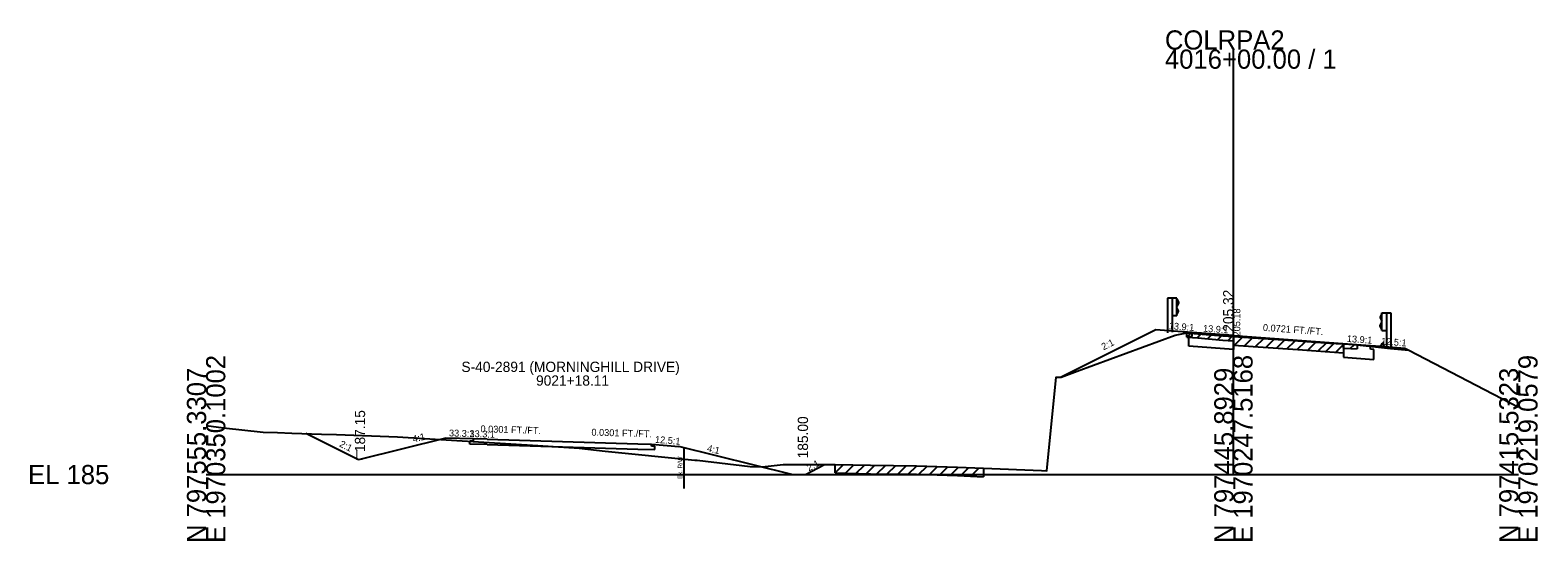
# Model space of a CAD drawing. Extents: x -26 to 1971083, y -10 to 798159.
# Drawn here: x -25.7 to 194.5, y 490.3 to 564.9 of the extents above; entities that cross this region are included whole.
import ezdxf

# ---------------------------------------------------------------- set-up
doc = ezdxf.new("R2010")
doc.units = 0
for name, color, linetype in [('RD_GPK_XS_Cell', 7, 'Continuous'), ('RD_XS_Base', 7, 'Continuous'), ('RD_XS_CurbTop', 7, 'Continuous'), ('RD_XS_EarthShd', 7, 'Continuous'), ('RD_XS_ExGround', 7, 'Continuous'), ('RD_XS_ExPaveRet', 7, 'Continuous'), ('RD_XS_ExRW', 7, 'Continuous'), ('RD_XS_GR', 7, 'Continuous'), ('RD_XS_Misc_Line', 7, 'Continuous'), ('RD_XS_Pave', 7, 'Continuous'), ('RD_XS_PaveOvlay', 7, 'Continuous'), ('RD_XS_PaveShd', 7, 'Continuous'), ('RD_XS_TieSlope', 7, 'Continuous'), ('RD_XS_TX_Elev_EX', 7, 'Continuous'), ('RD_XS_TX_Elev_PR', 7, 'Continuous'), ('RD_XS_TX_Misc', 7, 'Continuous'), ('RD_XS_TX_MkPT', 7, 'Continuous'), ('RD_XS_TX_Profile', 7, 'Continuous'), ('RD_XS_TX_ShdSlope', 7, 'Continuous'), ('RD_XS_TX_Slope', 7, 'Continuous'), ('RD_XS_TX_Station', 7, 'Continuous')]:
    doc.layers.add(name, color=color, linetype=linetype)

msp = doc.modelspace()

# ---------------------------------------------------------------- linework, layer by layer
at = {"layer": 'RD_GPK_XS_Cell'}
for p, q in [((150, 500), (150, 562.11)), ((0, 500), (150, 500)), ((150, 500), (191.61, 500))]:
    msp.add_line(p, q, dxfattribs=at)
at = {"layer": 'RD_XS_Base'}
for p, q in [((143.5, 520.22), (144, 520.19)), ((143.5, 518.74), (143.5, 520.22)), ((144, 520.19), (144, 520.75)), ((150, 518.28), (143.5, 518.74)), ((170, 518.32), (170, 518.88)), ((170.5, 518.29), (170, 518.32)), ((170.5, 516.81), (170.5, 518.29)), ((166.09, 517.13), (170.5, 516.81)), ((38.52, 504.94), (39.02, 504.92)), ((38.52, 504.46), (38.52, 504.94)), ((41.02, 504.38), (38.52, 504.46)), ((39.02, 504.92), (39.02, 505.22)), ((41.02, 504.38), (52.02, 504.05)), ((65.02, 504.14), (65.02, 504.44)), ((65.52, 504.13), (65.02, 504.14)), ((52.02, 504.05), (63.02, 503.72)), ((63.02, 503.72), (65.52, 503.65)), ((65.52, 503.65), (65.52, 504.13))]:
    msp.add_line(p, q, dxfattribs=at)
at = {"layer": 'RD_XS_CurbTop'}
for p, q in [((171.53, 518.76), (171.78, 519.22)), ((171.53, 518.76), (172, 518.72)), ((172, 518.72), (171.94, 519.16))]:
    msp.add_line(p, q, dxfattribs=at)
msp.add_ellipse((171.85, 519.14), major_axis=(0, -0.131), ratio=0.686, start_param=1.762783, end_param=4.036677, dxfattribs=at)
at = {"layer": 'RD_XS_EarthShd'}
for p, q in [((144, 520.75), (141.88, 520.9)), ((170, 518.88), (171.53, 518.76)), ((39.02, 505.22), (35.02, 505.34)), ((65.02, 504.44), (69.03, 504.12))]:
    msp.add_line(p, q, dxfattribs=at)
at = {"layer": 'RD_XS_ExGround'}
msp.add_lwpolyline([(0, 507.19), (2.56, 506.82), (8.31, 506.19), (10.4, 506.16), (12.53, 506.06), (16.84, 505.92), (19.06, 505.83), (27.94, 505.51), (48.43, 504.25), (54.48, 503.85), (58.26, 503.4), (71.34, 502.12), (71.72, 502.09), (79.42, 501.2), (81.17, 501.13), (84.26, 501.45), (87.97, 501.45), (91.83, 501.48), (97.02, 501.36), (103.75, 501.29), (109.72, 501.09), (113.53, 500.93), (121.98, 500.6), (122.78, 500.56), (124.1, 514.22), (124.86, 514.24), (127.19, 515.11), (141.51, 520.37), (143.22, 520.7), (144.82, 520.58), (148.46, 520.29), (150, 520.18), (159.4, 519.53), (165, 519.14), (166.23, 519.08), (168.07, 518.98), (172.94, 518.44), (175.63, 518.18), (191.61, 509.86)], dxfattribs=at)
at = {"layer": 'RD_XS_ExPaveRet'}
for p, q in [((143.22, 520.08), (143.22, 520.7)), ((143.22, 520.08), (144.82, 519.96)), ((144.82, 519.96), (148.46, 519.66)), ((148.46, 519.66), (150, 519.56)), ((150, 518.93), (150, 520.18)), ((150, 520.18), (150, 519.56)), ((150, 518.93), (159.4, 518.28)), ((159.4, 518.28), (166.09, 517.81)), ((166.09, 519.09), (166.09, 517.84)), ((166.09, 518.47), (166.09, 519.09)), ((166.09, 518.47), (166.23, 518.46)), ((166.23, 518.46), (168.07, 518.36)), ((168.07, 518.98), (168.07, 518.36)), ((91.83, 500.23), (91.83, 501.48)), ((91.83, 500.23), (97.02, 500.11)), ((97.02, 500.11), (103.75, 500.04)), ((103.75, 500.04), (109.72, 499.84)), ((109.72, 499.84), (113.53, 499.68)), ((113.53, 500.93), (113.53, 499.68))]:
    msp.add_line(p, q, dxfattribs=at)
at = {"layer": 'RD_XS_ExRW'}
msp.add_line((69.77, 503.96), (69.77, 497.96), dxfattribs=at)
at = {"layer": 'RD_XS_GR'}
for p, q in [((141.07, 525.77), (140.4, 525.77)), ((140.4, 525.77), (140.4, 520.72)), ((141.73, 525.77), (141.07, 525.77)), ((141.07, 525.77), (141.07, 520.83)), ((141.73, 523.21), (141.73, 525.77)), ((141.73, 525.61), (142, 525.17)), ((142, 525.06), (141.73, 524.62)), ((142, 523.92), (141.73, 524.36)), ((142, 525.17), (142, 525.06)), ((141.73, 523.21), (141.07, 523.21)), ((141.73, 523.37), (142, 523.81)), ((142, 523.81), (142, 523.92)), ((171.68, 523.47), (171.41, 523.03)), ((171.41, 523.03), (171.41, 522.92)), ((171.41, 522.92), (171.68, 522.48)), ((171.41, 521.78), (171.68, 522.22)), ((171.41, 521.67), (171.41, 521.78)), ((171.68, 523.64), (172.35, 523.64)), ((171.68, 521.07), (171.68, 523.64)), ((172.35, 523.64), (173.01, 523.64)), ((172.35, 523.64), (172.35, 518.69)), ((173.01, 523.64), (173.01, 518.58)), ((171.68, 521.23), (171.41, 521.67)), ((171.68, 521.07), (172.35, 521.07))]:
    msp.add_line(p, q, dxfattribs=at)
at = {"layer": 'RD_XS_Misc_Line'}
for p, q in [((143.22, 520.08), (143.8, 520.66)), ((144.72, 519.96), (145.3, 520.54)), ((146.22, 519.84), (146.8, 520.42)), ((147.72, 519.72), (148.3, 520.3)), ((149.23, 519.61), (149.81, 520.2)), ((150.14, 518.92), (151.31, 520.09)), ((151.64, 518.82), (152.81, 519.99)), ((153.23, 518.71), (154.42, 519.87)), ((154.76, 518.6), (155.94, 519.77)), ((156.28, 518.49), (157.47, 519.66)), ((157.81, 518.39), (159, 519.56)), ((159.33, 518.28), (160.52, 519.45)), ((160.86, 518.18), (162.05, 519.34)), ((162.39, 518.07), (163.58, 519.24)), ((163.48, 517.99), (164.65, 519.16)), ((164.97, 517.89), (166.17, 519.09)), ((167.07, 518.41), (167.66, 519)), ((91.83, 500.23), (93.07, 501.46)), ((93.36, 500.2), (94.6, 501.42)), ((94.88, 500.16), (96.12, 501.38)), ((96.41, 500.13), (97.66, 501.36)), ((97.93, 500.1), (99.19, 501.34)), ((99.46, 500.09), (100.72, 501.32)), ((100.99, 500.07), (102.25, 501.31)), ((102.51, 500.05), (103.77, 501.29)), ((104.04, 500.03), (105.27, 501.24)), ((105.57, 499.98), (106.8, 501.19)), ((107.09, 499.93), (108.32, 501.14)), ((108.62, 499.88), (109.85, 501.08)), ((110.15, 499.82), (111.37, 501.02)), ((111.67, 499.76), (112.89, 500.96))]:
    msp.add_line(p, q, dxfattribs=at)
at = {"layer": 'RD_XS_Pave'}
for p, q in [((150, 520.32), (166, 519.17)), ((41.02, 505.16), (52.02, 504.83)), ((52.02, 504.83), (63.02, 504.5))]:
    msp.add_line(p, q, dxfattribs=at)
at = {"layer": 'RD_XS_PaveOvlay'}
for p, q in [((150, 520.18), (150, 518.27)), ((153.23, 519.96), (159.4, 519.53)), ((159.4, 519.53), (164.07, 519.2)), ((164.07, 519.2), (166.09, 519.09)), ((166.09, 519.09), (166.09, 517.13))]:
    msp.add_line(p, q, dxfattribs=at)
at = {"layer": 'RD_XS_PaveShd'}
for p, q in [((150, 520.32), (144, 520.75)), ((166, 519.17), (170, 518.88)), ((41.02, 505.16), (39.02, 505.22)), ((63.02, 504.5), (65.02, 504.44))]:
    msp.add_line(p, q, dxfattribs=at)
at = {"layer": 'RD_XS_TieSlope'}
for p, q in [((138.65, 521.13), (124.86, 514.24)), ((141.88, 520.9), (138.65, 521.13)), ((171.53, 518.76), (175.03, 518.48)), ((175.02, 518.48), (175.63, 518.18)), ((22.25, 502.15), (14.56, 506)), ((35.02, 505.34), (22.25, 502.15)), ((85.51, 500), (69.03, 504.12)), ((85.51, 500), (87.51, 500)), ((87.51, 500), (90.28, 501.47))]:
    msp.add_line(p, q, dxfattribs=at)

# ---------------------------------------------------------------- texts
at = {"layer": 'RD_GPK_XS_Cell'}
for s, p in [('COLRPA2', (140, 562.11)), ('4016+00.00 / 1', (140, 559.31)), ('EL 185', (-26, 498.6))]:
    msp.add_text(s, height=2.8, dxfattribs=at).set_placement(p)
for s, p in [('N 797555.3307', (0, 490)), ('E 1970350.1002', (2.8, 490)), ('N 797445.8929', (150, 490)), ('E 1970247.5168', (152.8, 490)), ('N 797415.5323', (191.61, 490)), ('E 1970219.0579', (194.41, 490))]:
    msp.add_text(s, height=2.8, rotation=90, dxfattribs=at).set_placement(p)
at = {"layer": 'RD_XS_ExRW'}
msp.add_text('Ex. R/W ', height=0.65, rotation=90, dxfattribs=at).set_placement((69.52, 499.35))
at = {"layer": 'RD_XS_TX_Elev_EX'}
msp.add_text('205.18', height=1, rotation=90, dxfattribs=at).set_placement((151, 520.18))
at = {"layer": 'RD_XS_TX_Elev_PR'}
msp.add_text(' 205.32', height=1.5, rotation=90, dxfattribs=at).set_placement((150, 520.32))
at = {"layer": 'RD_XS_TX_Misc'}
for s, p in [('187.15', (23.22, 503.28)), ('185.00', (87.89, 502.37))]:
    msp.add_text(s, height=1.5, rotation=90, dxfattribs=at).set_placement(p)
at = {"layer": 'RD_XS_TX_MkPT'}
msp.add_text('L', height=1.5, dxfattribs=at).set_placement((21.75, 502.15))
at = {"layer": 'RD_XS_TX_Profile'}
msp.add_text('33.3:1', height=1, rotation=358.2787, dxfattribs=at).set_placement((38.45, 505.49))
at = {"layer": 'RD_XS_TX_ShdSlope'}
for s, rotation, p in [('13.9:1', 355.898, (140.54, 521.25)), ('12.5:1', 355.4261, (171.54, 519.01)), ('33.3:1', 358.2787, (35.45, 505.58)), ('12.5:1', 355.4323, (65.52, 504.65))]:
    msp.add_text(s, height=1, rotation=rotation, dxfattribs=at).set_placement(p)
at = {"layer": 'RD_XS_TX_Slope'}
for s, rotation, p in [('13.9:1', 355.898, (145.54, 520.89)), ('0.0721 FT./FT.', 355.898, (154.28, 521.01)), ('2:1', 26.5651, (131.03, 518.15)), ('13.9:1', 355.898, (166.54, 519.38)), ('0.0301 FT./FT.', 358.2787, (40.05, 506.19)), ('0.0301 FT./FT.', 358.2787, (56.25, 505.7)), ('2:1', 333.435, (19.37, 504.15)), ('4:1', 14.0362, (30.28, 504.67)), ('4:1', 346.9381, (73.07, 503.4)), ('2:1', 27.927, (88.02, 500.46))]:
    msp.add_text(s, height=1, rotation=rotation, dxfattribs=at).set_placement(p)
at = {"layer": 'RD_XS_TX_Station'}
for s, p in [('S-40-2891 (MORNINGHILL DRIVE)', (37.28, 514.99)), ('9021+18.11', (48.18, 512.99))]:
    msp.add_text(s, height=1.5, dxfattribs=at).set_placement(p)

doc.saveas('drawing.dxf')
